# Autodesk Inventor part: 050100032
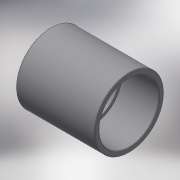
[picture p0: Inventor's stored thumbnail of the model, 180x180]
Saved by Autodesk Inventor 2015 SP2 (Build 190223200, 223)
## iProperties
Created: 2017-10
Part Number: 050100032
Material: Generic
Description: PLASSON SOCKET PVC 32 - CEMENT
Document SubType Name: Modeling
Designer: KIM
Density: 1 g/cm^3
Appearance: Default
Author: KIM
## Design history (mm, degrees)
derived "050100.ipt"
feature "Solid1::050100.ipt"
tag "TaggingFeature1"
body "Solid1"
other parameters: "d0" = 48, "d1" = 38, "d2" = 22, "d3" = 4, "d4" = 32, "d5" = 28.8, "d7" = 0.32, "d_" = 32, "E_" = 38, "H_" = 48, "l_" = 22, "Z_" = 4
